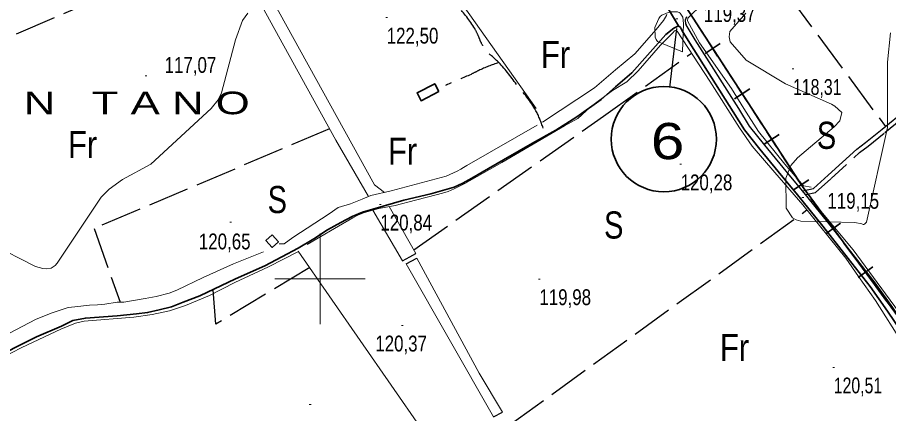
# Model space of a CAD drawing. Extents: x 483847 to 488453, y 4383581 to 4386795.
# Drawn here: x 486832.5 to 487314.7, y 4385925.5 to 4386144.6 of the extents above; entities that cross this region are included whole.
import ezdxf
from ezdxf.enums import TextEntityAlignment as Align

# ---------------------------------------------------------------- set-up
doc = ezdxf.new("R2010")
doc.units = 0
doc.header["$LTSCALE"] = 3.8
doc.linetypes.add('LONG_DASHED', pattern=[7.5, 6, -1.5])
doc.linetypes.add('MEDIUM_DASHED', pattern=[4.5, 3, -1.5])
for name, color, linetype, lineweight in [('1', 7, 'Continuous', 13), ('13', 7, 'Continuous', 25), ('25', 7, 'LONG_DASHED', 25), ('34', 7, 'Continuous', 35), ('36', 7, 'Continuous', 25), ('38', 7, 'Continuous', 25), ('47', 7, 'Continuous', 35), ('51', 7, 'Continuous', 13), ('6', 7, 'Continuous', 35), ('7', 7, 'Continuous', 13), ('9', 7, 'Continuous', 13)]:
    doc.layers.add(name, color=color, linetype=linetype, lineweight=lineweight)
doc.layers.add('31', color=7, linetype='Continuous')
doc.layers.add('5', color=7, linetype='Continuous')

msp = doc.modelspace()

# ---------------------------------------------------------------- linework, layer by layer
at = {"layer": '1'}
for p, q in [((487000, 4386025), (487000, 4385975)), ((486975, 4386000), (487025, 4386000))]:
    msp.add_line(p, q, dxfattribs=at)
at = {"layer": '25'}
for p, q in [((487241.63, 4386180.58), (487312.95, 4386084.28)), ((487105.17, 4385919.43), (487269.58, 4386038.16))]:
    msp.add_line(p, q, dxfattribs=at)
for points in [[(486753.44, 4386101.87), (486947.36, 4386184.98), (486944.51, 4386198.88)], [(487051.87, 4386016.08), (487156.93, 4386089.98), (487205.69, 4386124.76)], [(487005.26, 4386082.95), (486875.03, 4386027.84), (486889.29, 4385987.15)], [(486994.27, 4386006.21), (486942.4, 4385974.95), (486940.88, 4385993.96)]]:
    msp.add_lwpolyline(points, dxfattribs=at)
at = {"layer": '34'}
for p, q in [((487206.5, 4386144.18), (487211.94, 4386135.8)), ((487221.58, 4386130.14), (487213.19, 4386124.69)), ((487214.66, 4386131.61), (487220.11, 4386123.22)), ((487222.83, 4386119.03), (487228.27, 4386110.64)), ((487230.99, 4386106.46), (487236.44, 4386098.07)), ((487237.91, 4386104.99), (487229.52, 4386099.54)), ((487239.16, 4386093.88), (487244.61, 4386085.49)), ((487247.32, 4386081.3), (487252.77, 4386072.92)), ((487254.24, 4386079.83), (487245.85, 4386074.39)), ((487255.49, 4386068.72), (487260.94, 4386060.34)), ((487270.57, 4386054.68), (487262.18, 4386049.23)), ((487272.26, 4386043.87), (487278.19, 4386035.82)), ((487288.14, 4386030.75), (487280.09, 4386024.81)), ((487281.15, 4386031.81), (487287.09, 4386023.76)), ((487290.05, 4386019.73), (487295.99, 4386011.68)), ((487305.94, 4386006.61), (487297.89, 4386000.67)), ((487298.95, 4386007.67), (487304.88, 4385999.62)), ((487307.85, 4385995.59), (487313.79, 4385987.54))]:
    msp.add_line(p, q, dxfattribs=at)
for points in [[(487280.6, 4386441.97), (487080, 4386339), (487267, 4386051), (487354, 4385933), (487441, 4385795), (487598, 4385523), (487650, 4385422), (487680.1, 4385371.64)], [(487263.66, 4386056.15), (487267, 4386051), (487269.29, 4386047.89)]]:
    msp.add_lwpolyline(points, dxfattribs=at)
at = {"layer": '36'}
for points in [[(487202.96, 4386144.85), (487202.16, 4386143.03), (487202.32, 4386141.06), (487202.6, 4386140.43)], [(487358.54, 4385915.9), (487338.89, 4385947.77), (487325.29, 4385971.97), (487317.06, 4385984.1), (487307.34, 4385997.88), (487295.19, 4386013.52), (487281.19, 4386031.35), (487266.37, 4386049.66), (487260.62, 4386056.41), (487246.31, 4386073.87), (487237.82, 4386084.5), (487231.82, 4386094.27), (487207.74, 4386132.21), (487202.6, 4386140.43)]]:
    msp.add_lwpolyline(points, dxfattribs=at)
at = {"layer": '38', "linetype": 'MEDIUM_DASHED'}
msp.add_line((487047.72, 4386008.39), (487053.58, 4386011.35), dxfattribs=at)
at = {"layer": '38'}
msp.add_line((487096.12, 4385923.65), (487101.02, 4385926.32), dxfattribs=at)
for points in [[(487267.16, 4386048.73), (487273.13, 4386050), (487281.27, 4386057.33), (487297.14, 4386071.79), (487301.95, 4386075.35), (487311.11, 4386082.77), (487324.22, 4386093.52), (487334.63, 4386102.82), (487358.73, 4386122.76), (487389.79, 4386148.06), (487409.89, 4386163.74), (487428.65, 4386179.91), (487447.11, 4386194.51), (487482.18, 4386222.75), (487500.55, 4386237.39), (487502.78, 4386238.42), (487505.91, 4386238.28), (487509.94, 4386236.9), (487526.59, 4386226.67)], [(487045.63, 4386010), (487049.8, 4386012.1), (487053.04, 4386014.03)]]:
    msp.add_lwpolyline(points, dxfattribs=at)
at = {"layer": '38', "linetype": 'MEDIUM_DASHED'}
msp.add_lwpolyline([(487268.88, 4386046.56), (487274.3, 4386047.71), (487282.94, 4386055.49), (487298.72, 4386069.87), (487303.47, 4386073.38), (487312.68, 4386080.85), (487325.84, 4386091.63), (487336.25, 4386100.94), (487360.3, 4386120.84), (487391.34, 4386146.12), (487411.46, 4386161.82), (487430.23, 4386177.99), (487448.66, 4386192.57), (487450.87, 4386194.35)], dxfattribs=at)
at = {"layer": '38', "linetype": 'LONG_DASHED'}
for points in [[(487123.54, 4386083.41), (487119.53, 4386093), (487108.86, 4386107.48), (487098.16, 4386120.39), (487092.02, 4386126.26), (487089.16, 4386130.72), (487087.85, 4386133.82), (487085.66, 4386138.35), (487076.09, 4386150.87), (487074.32, 4386153.15), (487073.37, 4386155.26), (487069.79, 4386167.02), (487068.39, 4386168.84), (487063.3, 4386175.07), (487059.71, 4386180.59), (487057.04, 4386183.11), (487053.34, 4386186.46), (487042.06, 4386185.2), (487040.93, 4386184.54)], [(487098.82, 4386119.61), (487087.88, 4386115.21), (487083.58, 4386113.09), (487070.66, 4386107.5), (487069.61, 4386106.99)]]:
    msp.add_spline(points, degree=3, dxfattribs=at)
at = {"layer": '47'}
for points in [[(487065.81, 4386103.52), (487055.99, 4386098.47), (487053.72, 4386102.87), (487063.54, 4386107.92)], [(486973.5, 4386024.33), (486976.99, 4386020.39), (486973.55, 4386017.35), (486970.06, 4386021.29)]]:
    msp.add_lwpolyline(points, close=True, dxfattribs=at)
at = {"layer": '51'}
for p, q in [((487045.63, 4386010), (487029.3, 4386037.99)), ((487038.23, 4386039.94), (487053.04, 4386014.03)), ((487096.12, 4385923.65), (487047.72, 4386008.39))]:
    msp.add_line(p, q, dxfattribs=at)
for points in [[(487316.97, 4386256.97), (487308.5, 4386247.04), (487298.06, 4386235.78), (487292.64, 4386229.56), (487283.88, 4386220.08), (487277.41, 4386213.64), (487268.58, 4386205.22), (487259.61, 4386196.86), (487246.38, 4386184.9), (487228.59, 4386168.72), (487203.55, 4386144.24), (487203.46, 4386142.67), (487210.03, 4386130.42), (487227.83, 4386105.33), (487234.58, 4386094.27), (487242.65, 4386081.55), (487257.32, 4386063.48), (487267.58, 4386051.48), (487271.92, 4386050.67)], [(487119.62, 4386094.12), (487076.67, 4386154.99), (487148.97, 4386205.05)], [(487035.65, 4386047.78), (487030.17, 4386051.95), (486977, 4386148.01), (486959.09, 4386181.51)], [(486954.06, 4386175.88), (487008.69, 4386076.72), (487026.89, 4386045.61)], [(487191.96, 4386146.43), (487191.72, 4386145.54), (487190.18, 4386142.93), (487186.13, 4386137.89), (487174.23, 4386124.48), (487163.52, 4386115.55), (487151.98, 4386105.66), (487123.22, 4386086.7)], [(487188.43, 4386129.15), (487195.26, 4386136.11), (487196.25, 4386137.07), (487196.85, 4386137.28), (487197.71, 4386136.96)], [(487341.47, 4385934.94), (487322.39, 4385964.48), (487307.49, 4385988.1), (487298, 4386001.37), (487291.17, 4386011.37), (487267.36, 4386040.9), (487251.85, 4386058.76), (487239.31, 4386073.42), (487232.25, 4386083.5), (487215.81, 4386109.25), (487197.71, 4386136.96)], [(486992.93, 4386019.02), (487007.99, 4386027.81), (487018.13, 4386033.74), (487021.38, 4386035.35), (487024.63, 4386036.65), (487032.61, 4386038.94), (487041.64, 4386040.54), (487052.79, 4386043.53), (487065.06, 4386046.58), (487069.06, 4386047.72), (487070.87, 4386048.22), (487074.34, 4386049.75), (487080.23, 4386052.66), (487100.66, 4386064.38), (487135.32, 4386084.59), (487142.66, 4386088.69), (487149.57, 4386094.89), (487161.86, 4386104.09), (487169.88, 4386109.01), (487176.2, 4386115.07), (487188.43, 4386129.15)], [(486977.41, 4386019.39), (486980.18, 4386019.43), (486984.96, 4386022.81), (487005.11, 4386035.88), (487010.04, 4386039.41), (487016.89, 4386041.42), (487023.31, 4386044.1), (487028.14, 4386046.13), (487039.36, 4386048.6), (487069.79, 4386056.79), (487075.98, 4386059.55), (487077.95, 4386060.58), (487079.46, 4386061.53), (487081.35, 4386062.63), (487120.19, 4386084.94)], [(487413.87, 4385949.66), (487401.01, 4385942.04), (487379.51, 4385924.12), (487362.29, 4385911.16), (487362.08, 4385911.98), (487349.33, 4385933.4), (487335.84, 4385955.36), (487322.8, 4385977.45), (487320.75, 4385981.23), (487313.02, 4385991.63), (487295.14, 4386016.12), (487271.75, 4386044.14)], [(486988.04, 4386015.18), (486971.4, 4386006.6), (486952.84, 4385997.91), (486938.78, 4385990.73), (486925.61, 4385985.34), (486916.63, 4385982.35), (486907.05, 4385980.25), (486896.88, 4385978.75), (486869.35, 4385976.66), (486864.56, 4385975.46), (486856.48, 4385972.17), (486834.93, 4385961.99), (486811.89, 4385950.31), (486794.83, 4385940.73), (486780.17, 4385932.35), (486775.38, 4385930.55), (486765.5, 4385926.66), (486724.21, 4385906.3), (486721.51, 4385904.8), (486723.09, 4385903.28)], [(486764.64, 4385938.4), (486765.91, 4385937.41), (486767.25, 4385937.24), (486770.56, 4385937.34), (486827.74, 4385969.74), (486842.95, 4385977.8), (486851.63, 4385981.28), (486860.67, 4385984.07), (486864.28, 4385984.62), (486872.32, 4385985.48), (486876.75, 4385985.64), (486880.81, 4385986.04), (486887.73, 4385987.14), (486891.48, 4385987.16), (486903.29, 4385989.17), (486909.23, 4385990.21), (486916.54, 4385992.13), (486920.76, 4385993.72), (486935.27, 4386000.79), (486952.19, 4386008.35), (486968.79, 4386015.02)], [(486987.93, 4386015.34), (487090.78, 4385867.1), (487082.8, 4385859.78), (487151.52, 4385753.97), (487218.16, 4385655.55), (487224.75, 4385659.88), (487236.21, 4385668.34)], [(487053.58, 4386011.35), (487088.19, 4385947.8), (487101.02, 4385926.32)]]:
    msp.add_lwpolyline(points, dxfattribs=at)
at = {"layer": '6', "lineweight": 25}
msp.add_line((487197.33, 4386138.44), (487193.45, 4386105.77), dxfattribs=at)
at = {"layer": '6'}
for points in [[(487033.84, 4386323.76), (487042.5, 4386325.14), (487053.91, 4386325.94), (487058.85, 4386325.87), (487063.33, 4386324.69), (487066.47, 4386324.42), (487068.98, 4386323.12), (487070.31, 4386321.9), (487077.31, 4386314.01), (487084.56, 4386306.18), (487090.4, 4386295.22), (487099.73, 4386280.83), (487110.28, 4386263.12), (487116.59, 4386253.34), (487122.76, 4386244.17), (487131.94, 4386235.26), (487139.31, 4386226.08), (487158.04, 4386203.31), (487181.5, 4386168.37), (487198.43, 4386139.94)], [(487195.78, 4386138.66), (487198.43, 4386139.98), (487199.62, 4386138.92), (487200.54, 4386137.06)], [(486816.11, 4385954.4), (486842.97, 4385967.98), (486856.8, 4385973.84), (486863.2, 4385976.89), (486870.1, 4385978.29), (486887.62, 4385979.51), (486898.46, 4385980.58), (486904.53, 4385981.38), (486911.03, 4385982.92), (486917.86, 4385984.51), (486924.28, 4385987.17), (486933.54, 4385990.54), (486953.2, 4386000.02), (486969.46, 4386007.19), (486978.94, 4386012.25), (486987.97, 4386017.06), (486996.64, 4386022.22), (487004.16, 4386027.04), (487011.57, 4386031.23), (487017.83, 4386034.46), (487023.45, 4386036.93), (487034.88, 4386040.13), (487046.43, 4386043.6), (487061.36, 4386047.05), (487074.18, 4386050.65), (487079.1, 4386052.94), (487083.98, 4386055.69), (487089.78, 4386059), (487101.5, 4386065.89), (487117.69, 4386075.07), (487130.52, 4386082.16), (487142.14, 4386089.51), (487155.67, 4386099.18), (487163.6, 4386106.12), (487172.67, 4386113.9), (487191.42, 4386135.09), (487195.78, 4386138.66)], [(487355.43, 4385914.12), (487335.81, 4385945.95), (487322.23, 4385970.08), (487314.11, 4385982.06), (487304.47, 4385995.75), (487292.37, 4386011.32), (487278.39, 4386029.12), (487263.61, 4386047.36), (487257.87, 4386054.11), (487243.52, 4386071.62), (487234.89, 4386082.44), (487228.78, 4386092.37), (487204.73, 4386130.27), (487200.54, 4386137.07)]]:
    msp.add_lwpolyline(points, dxfattribs=at)
msp.add_circle((487190.32, 4386077.26), 29.1, dxfattribs=at)
at = {"layer": '7'}
for p, q in [((487036.4, 4386144.45), (487037.4, 4386144.45)), ((487197.05, 4386143.8), (487198.05, 4386143.8)), ((487261.33, 4386116.09), (487262.33, 4386116.09)), ((486903.2, 4386112.22), (486904.2, 4386112.22)), ((487199.12, 4386063.33), (487200.12, 4386063.33)), ((487266.76, 4386044.96), (487267.76, 4386044.96)), ((487032.9, 4386041.1), (487033.9, 4386041.1)), ((486950.07, 4386031.41), (486951.07, 4386031.41)), ((487120.92, 4385999.85), (487121.92, 4385999.85)), ((487045.07, 4385974.22), (487046.07, 4385974.22)), ((487283.88, 4385951.07), (487284.88, 4385951.07)), ((486994.02, 4385930.53), (486995.02, 4385930.53))]:
    msp.add_line(p, q, dxfattribs=at)
at = {"layer": '9'}
for points in [[(486817.77, 4386019.41), (486842.5, 4386006.79), (486846.59, 4386005.75), (486848.45, 4386005.55), (486851.1, 4386005.87), (486853.3, 4386007.33), (486854.54, 4386008.73), (486878.87, 4386045.2), (486883.23, 4386049.68), (486890.74, 4386054.88), (486906.28, 4386063.43), (486939.66, 4386094.17), (486943.6, 4386099.07), (486945.37, 4386102.86), (486953.28, 4386132.14), (486957.11, 4386142.84), (486960.02, 4386146.94)], [(487315.89, 4386136), (487314.18, 4386119.75), (487314.13, 4386083.7), (487302.5, 4386031.41), (487301.32, 4386030.25), (487301.02, 4386030.11), (487300.74, 4386030.05), (487299.86, 4386030.48), (487296.15, 4386031.15), (487266.08, 4386031.92), (487263.61, 4386032.68), (487261.58, 4386033.66), (487258.06, 4386039.05), (487257.86, 4386055.76), (487260.68, 4386062.62), (487264.33, 4386066.96), (487284.61, 4386083.97), (487287.68, 4386087.47), (487288.8, 4386091.92), (487284.98, 4386095.44), (487283.17, 4386096.53), (487257.71, 4386107.88), (487235.95, 4386120.97), (487226.99, 4386131.06), (487226.53, 4386133.87), (487226.94, 4386136.7), (487235.71, 4386146.95)]]:
    msp.add_lwpolyline(points, dxfattribs=at)
msp.add_lwpolyline([(487200.61, 4386125.62), (487186.91, 4386131.28), (487186.06, 4386132.37), (487185.46, 4386133.57), (487185.31, 4386138.92), (487187.49, 4386143.99), (487188.34, 4386145.01), (487189.31, 4386145.88), (487193.71, 4386147.64), (487197.91, 4386147.63), (487198.75, 4386147.37), (487199.46, 4386147), (487200.83, 4386144.78), (487201.14, 4386141.23)], close=True, dxfattribs=at)

# ---------------------------------------------------------------- texts
at = {"layer": '13', "width": 1.25}
msp.add_text('6', height=20, dxfattribs=at).set_placement((487192.42, 4386066.19), align=Align.CENTER)
at = {"layer": '31'}
for s, width, p in [('Fr', 0.85, (487130.35, 4386116.58)), ('S', 0.8, (487280.4, 4386071.88)), ('Fr', 0.85, (486868.58, 4386066.82)), ('Fr', 0.85, (487045.68, 4386063.12)), ('S', 0.8, (486976.35, 4386036.35)), ('S', 0.8, (487162.6, 4386022.29)), ('Fr', 0.85, (487229.44, 4385954.55))]:
    msp.add_text(s, height=15, dxfattribs=dict(at, width=width)).set_placement(p, align=Align.CENTER)
at = {"layer": '5', "width": 1.45}
msp.add_text('S O N   T A N O', height=12.49, dxfattribs=at).set_placement((486961.1, 4386091.03), align=Align.RIGHT)
at = {"layer": '7'}
for s, width, p in [('119,37', 0.8, (487212.49, 4386142.09)), ('122,50', 0.8, (487036.9, 4386130.08)), ('117,07', 0.8, (486913.95, 4386113.89)), ('118,31', 0.75, (487261.83, 4386101.72)), ('120,28', 0.8, (487199.62, 4386048.96)), ('119,15', 0.8, (487280.88, 4386038.77)), ('120,84', 0.8, (487033.4, 4386026.73)), ('120,65', 0.8, (486932.92, 4386016.3)), ('119,98', 0.8, (487121.42, 4385985.48)), ('120,37', 0.8, (487030.58, 4385959.85)), ('120,51', 0.75, (487284.38, 4385936.7))]:
    msp.add_text(s, height=8.75, dxfattribs=dict(at, width=width)).set_placement(p)

doc.saveas('drawing.dxf')
